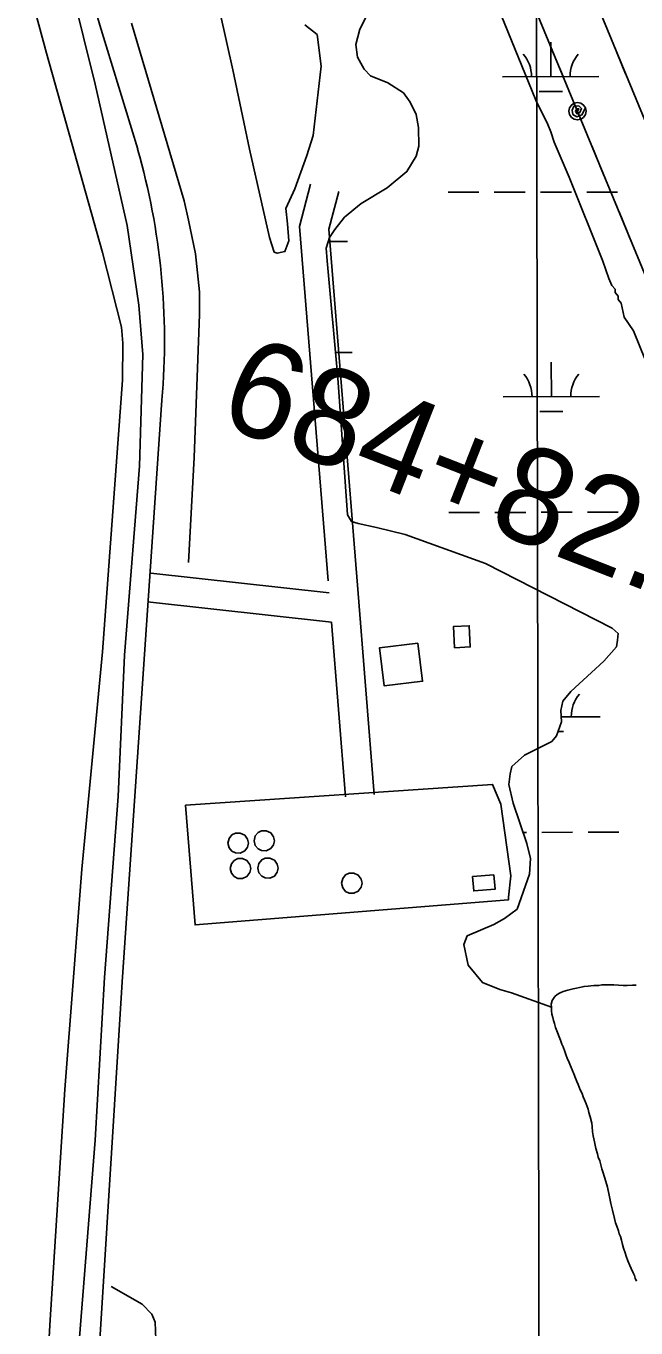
# Model space of a CAD drawing. Extents: x 3329297 to 3367176, y 649250 to 674653.
# Drawn here: x 3343401 to 3344034, y 663837 to 665190 of the extents above; entities that cross this region are included whole.
import ezdxf

# ---------------------------------------------------------------- set-up
doc = ezdxf.new("R2010")
doc.units = 0
for name, color, linetype in [('V-BLDG-OTLN', 7, 'Continuous'), ('V-DOMW-TANK', 7, 'Continuous'), ('V-DTCH-CNTR', 7, 'Continuous'), ('V-GRID-MAJR', 7, 'Continuous'), ('V-LEVE-TOET', 7, 'Continuous'), ('V-RAIL-TRAK', 7, 'Continuous'), ('V-ROAD-CNTR', 7, 'Continuous'), ('V-SITE-OTLN', 7, 'Continuous'), ('V-SITE-VEGE', 7, 'Continuous'), ('V-SURV-IDEN', 7, 'Continuous'), ('V-TOPO-SHOR', 7, 'Continuous'), ('V-UTIL-LINE', 7, 'Continuous'), ('V-WETL-SWMP', 7, 'Continuous')]:
    doc.layers.add(name, color=color, linetype=linetype)

msp = doc.modelspace()

# ---------------------------------------------------------------- linework, layer by layer
at = {"layer": 'V-BLDG-OTLN'}
for points in [[(3343846.2, 664544.3), (3343845.2, 664566.4), (3343861.4, 664567.2), (3343862.5, 664545.1)], [(3343808, 664549.2), (3343768.3, 664544.3), (3343773.2, 664504.6), (3343812.9, 664509.5)], [(3343864.9, 664306.4), (3343886.9, 664308.2), (3343888.2, 664293.3), (3343866.1, 664291.5)]]:
    msp.add_lwpolyline(points, close=True, dxfattribs=at)
at = {"layer": 'V-DOMW-TANK'}
for points in [[(3343659.2, 664343.7), (3343658.3, 664339.5), (3343655.3, 664335.5), (3343650.6, 664333.3), (3343645.8, 664333.4), (3343642.1, 664335.2), (3343639.1, 664338.7), (3343637.9, 664343.7), (3343639.1, 664348.7), (3343642.1, 664352.2), (3343645.8, 664354), (3343650.6, 664354.1), (3343655.3, 664351.9), (3343658.3, 664347.9)], [(3343632.1, 664341.3), (3343631.2, 664337), (3343628.2, 664333.1), (3343623.5, 664330.9), (3343618.7, 664331), (3343615, 664332.8), (3343612, 664336.3), (3343610.8, 664341.3), (3343612, 664346.2), (3343615, 664349.7), (3343618.7, 664351.6), (3343623.5, 664351.7), (3343628.2, 664349.5), (3343631.2, 664345.5)], [(3343634.5, 664314.9), (3343633.6, 664310.7), (3343630.6, 664306.7), (3343625.9, 664304.5), (3343621.1, 664304.6), (3343617.4, 664306.4), (3343614.4, 664309.9), (3343613.2, 664314.9), (3343614.4, 664319.8), (3343617.4, 664323.3), (3343621.1, 664325.2), (3343625.9, 664325.3), (3343630.6, 664323.1), (3343633.6, 664319.1)], [(3343663, 664315.2), (3343662.1, 664311), (3343659.1, 664307), (3343654.4, 664304.8), (3343649.6, 664305), (3343645.9, 664306.8), (3343643, 664310.3), (3343641.7, 664315.2), (3343643, 664320.2), (3343645.9, 664323.7), (3343649.6, 664325.5), (3343654.4, 664325.7), (3343659.1, 664323.5), (3343662.1, 664319.5)], [(3343750.1, 664299.6), (3343749.2, 664295.4), (3343746.2, 664291.4), (3343741.6, 664289.2), (3343736.8, 664289.3), (3343733, 664291.1), (3343730.1, 664294.6), (3343728.8, 664299.6), (3343730.1, 664304.6), (3343733, 664308.1), (3343736.8, 664309.9), (3343741.6, 664310), (3343746.2, 664307.8), (3343749.2, 664303.8)]]:
    msp.add_lwpolyline(points, close=True, dxfattribs=at)
at = {"layer": 'V-DTCH-CNTR'}
msp.add_lwpolyline([(3343489.7, 663880.5), (3343521.9, 663862.1), (3343531.8, 663851.8), (3343535.3, 663843.5), (3343537.4, 663789.2)], dxfattribs=at)
at = {"layer": 'V-GRID-MAJR'}
msp.add_spline([(3343949.3, 654651.9), (3343938.7, 660710.3), (3343928.1, 666771.7), (3343917.5, 672833.1), (3343917.5, 672836.2)], degree=3, dxfattribs=at)
at = {"layer": 'V-LEVE-TOET'}
msp.add_lwpolyline([(3343370.7, 665352.2), (3343422.3, 665162.3), (3343480.5, 664955.1), (3343500.2, 664877.4), (3343501.8, 664860.7), (3343501.5, 664822.5), (3343480.6, 664539.9), (3343459, 664314.3), (3343441.6, 664085.3), (3343425.8, 663840.4), (3343416.1, 663664.3)], dxfattribs=at)
at = {"layer": 'V-RAIL-TRAK'}
msp.add_arc((6548955.2, 1986802.1), 3466661.3, 202.398581, 202.4578394, dxfattribs=at)
at = {"layer": 'V-ROAD-CNTR'}
for points in [[(3343517.1, 665062.6), (3343477.9, 665191.4), (3343226.6, 666055.4)], [(3343714.8, 664613.7), (3343685.3, 664982.1), (3343696.7, 665025.9)], [(3343745.3, 664609.4), (3343715.6, 664979.4), (3343725.8, 665018.3)], [(3342686.8, 661326.8), (3342880.4, 661699.3), (3342918.9, 661772.4), (3342948.3, 661828.8), (3342977.9, 661900.1), (3343023.9, 662012.4), (3343199.1, 662449.7), (3343275.6, 662640.2), (3343326.1, 662763), (3343367, 662863.5), (3343386, 662912), (3343401.5, 662954.3), (3343413.8, 662991.9), (3343422.4, 663033.5), (3343430.6, 663084.8), (3343436.9, 663168.9), (3343501.1, 664197), (3343542.3, 664801.7)], [(3343530.7, 664621.7), (3343715.8, 664601.3)], [(3343762.7, 664391.7), (3343745.3, 664609.4)], [(3343527.4, 664591.9), (3343718.3, 664570.8)], [(3343732.8, 664389.3), (3343718.3, 664570.8)]]:
    msp.add_lwpolyline(points, dxfattribs=at)
msp.add_arc((3342816.2, 664863.1), 728.7, 355.1633, 15.8856, dxfattribs=at)
at = {"layer": 'V-SITE-OTLN'}
msp.add_lwpolyline([(3343566.9, 664380.5), (3343885.6, 664402.3), (3343894.1, 664381.7), (3343904.7, 664307.2), (3343902.2, 664285.1), (3343902.2, 664282.4), (3343576.7, 664256.3)], close=True, dxfattribs=at)
at = {"layer": 'V-SITE-VEGE'}
msp.add_lwpolyline([(3343690.7, 665191.6), (3343703.4, 665181.5), (3343707.7, 665148.8), (3343699.2, 665076.6), (3343692.8, 665055.7), (3343680.2, 665021.2), (3343671, 665000.6), (3343672.7, 664984.8), (3343674.1, 664967.1), (3343669.9, 664956), (3343662.1, 664954.3), (3343658.9, 664955.5), (3343654, 664970.8), (3343633.2, 665062.4), (3343616, 665145), (3343589.7, 665263)], dxfattribs=at)
at = {"layer": 'V-TOPO-SHOR'}
for points in [[(3343454.9, 663805.6), (3343472.9, 664032.6), (3343482.6, 664201.5), (3343496.9, 664389.7), (3343503.4, 664536.4), (3343519, 664733), (3343522.5, 664849.2), (3343518.4, 664900.3), (3343506.3, 664983.2), (3343472.8, 665130), (3343437.1, 665275.5), (3343388.8, 665436.1)], [(3343570, 664632.7), (3343575.6, 664742), (3343581.4, 664890.7), (3343581.2, 664914.2), (3343577.2, 664953.6), (3343569.9, 664988.8), (3343565.5, 665008.8), (3343510.7, 665193.4)], [(3343970, 664101.5), (3343968.3, 664105.6), (3343966.4, 664109.6), (3343965, 664113.3), (3343963.1, 664117.9), (3343961.9, 664120.6), (3343960.7, 664124.6), (3343958.8, 664129.4), (3343957.6, 664132.4), (3343956.1, 664136.6), (3343954.7, 664139.8), (3343953, 664144.4), (3343951.1, 664149.7), (3343949.9, 664153.9), (3343948.9, 664156.9), (3343948, 664159.9), (3343947.2, 664163.6), (3343946.7, 664166.8), (3343946.7, 664170.8), (3343946.6, 664174), (3343947.5, 664177.7), (3343950.3, 664181.9), (3343952.8, 664183.8), (3343955.8, 664185.7), (3343959, 664187.1), (3343963.6, 664188.3), (3343969.2, 664189.8), (3343972.6, 664190.5), (3343975.9, 664191.3), (3343980.7, 664192.3), (3343984.7, 664192.5), (3343987.7, 664193), (3343990.7, 664193.3), (3343995.8, 664193.4), (3343999.2, 664193.9), (3344002.3, 664193.9), (3344006.2, 664194), (3344011.5, 664193.8), (3344016.2, 664193.6), (3344021.3, 664193.4), (3344025.5, 664193.3), (3344030.8, 664193.6), (3344034.7, 664193.6)], [(3344035, 663886), (3344033.8, 663889), (3344032.8, 663892), (3344031.6, 663894.8), (3344029.5, 663899.2), (3344028, 663902.2), (3344026.1, 663907.2), (3344024.2, 663912.1), (3344023.2, 663915.3), (3344021.6, 663920.2), (3344020.6, 663924.1), (3344019.4, 663928.5), (3344018.4, 663932.4), (3344017.2, 663935.2), (3344016.2, 663938.2), (3344014.6, 663943), (3344013.4, 663946.7), (3344012.1, 663951.1), (3344010, 663959.7), (3344008.5, 663966.6), (3344007, 663973.5), (3344004.8, 663983.7), (3344003.3, 663989.5), (3344001.9, 663994.1), (3344000.2, 663999.6), (3343999.2, 664002.6), (3343998.3, 664005.6), (3343996.8, 664011), (3343995.4, 664014.9), (3343994.4, 664018.3), (3343992.7, 664023.7), (3343992, 664027.4), (3343991.5, 664030.8), (3343990.2, 664037.1), (3343989.3, 664041), (3343989, 664046.8), (3343988.5, 664050.3), (3343987, 664056.7), (3343985.6, 664061.4), (3343984.8, 664064.8), (3343982.7, 664070.4), (3343981.2, 664074.3), (3343979.8, 664077.5), (3343978.6, 664081), (3343976.7, 664084.9), (3343974.5, 664090.2), (3343973.1, 664093.4), (3343971.7, 664097.1), (3343970, 664101.5)]]:
    msp.add_lwpolyline(points, dxfattribs=at)
at = {"layer": 'V-UTIL-LINE'}
for points in [[(3345932.1, 660508.5), (3345266.9, 662132.1), (3344424.6, 664170), (3343419, 666605.5), (3342586.6, 668628.9), (3341907.6, 670274.6), (3341535.6, 671146.2)], [(3341480.8, 671097), (3341874.4, 670184.1), (3342489.4, 668700.6), (3343600.8, 666004.9), (3344292.6, 664330.1), (3345012, 662588.2), (3345711.5, 660882.6)], [(3344092, 664724.5), (3344031.8, 664873.5), (3344022.3, 664888), (3344019.1, 664902.5), (3344015.9, 664906.2), (3344015.9, 664909.8), (3344012.8, 664913.4), (3344012.8, 664917.1), (3344009.6, 664920.7), (3344006.4, 664928), (3344000.1, 664946.2), (3343965.2, 665033.4), (3343958.9, 665047.9), (3343952.6, 665062.5), (3343949.4, 665069.7), (3343946.2, 665080.6), (3343943.1, 665087.9), (3343930.4, 665113.3), (3343800.5, 665433.1)], [(3343945.9, 665169.3), (3343958.9, 665137.9)], [(3344023.7, 665140.9), (3344010.8, 665172.3)], [(3343973.8, 665101.8), (3343975.3, 665104.3), (3343973, 665104.2), (3343971.6, 665101.8), (3343973, 665099.3), (3343976.2, 665100.4), (3343978.1, 665104.7), (3343975, 665107.6), (3343970.1, 665107), (3343968.2, 665102.9), (3343968.9, 665098.5), (3343973.2, 665096.2), (3343978.4, 665098), (3343982.1, 665105.3), (3343980.1, 665108.2), (3343977.2, 665110.2), (3343973.8, 665110.8), (3343970.3, 665110.2), (3343967.4, 665108.2), (3343965.5, 665105.3), (3343964.8, 665101.9), (3343965.4, 665098.4), (3343967.4, 665095.5), (3343970.3, 665093.5), (3343973.8, 665092.8), (3343977.2, 665093.5), (3343980.1, 665095.5), (3343982.1, 665098.4), (3343982.8, 665101.8), (3343982.1, 665105.3)], [(3343988.7, 665065.8), (3344001.6, 665034.3)], [(3344016.9, 664997.4), (3344029.9, 664965.9)]]:
    msp.add_lwpolyline(points, dxfattribs=at)
at = {"layer": 'V-WETL-SWMP'}
for p, q in [((3343946, 665137.8), (3343946, 665173.8)), ((3343896, 665137.7), (3343996, 665137.9)), ((3343934.1, 665122.4), (3343958.1, 665122.4)), ((3343839.4, 665017.6), (3343871.4, 665017.6)), ((3343887.4, 665017.7), (3343919.4, 665017.7)), ((3343935.4, 665017.7), (3343967.4, 665017.8)), ((3343983.4, 665017.8), (3344015.4, 665017.9)), ((3343715, 664966.6), (3343734.9, 664966.6)), ((3343722.5, 664851.2), (3343739.7, 664851.2)), ((3343946.7, 664805.2), (3343946.6, 664841.2)), ((3343896.7, 664805.1), (3343996.7, 664805.3)), ((3343934.7, 664789.7), (3343958.7, 664789.8)), ((3343840.1, 664684.9), (3343872.1, 664685)), ((3343888.1, 664685), (3343920.1, 664685)), ((3343936.1, 664685.1), (3343968.1, 664685.1)), ((3343984.1, 664685.2), (3344016.1, 664685.2)), ((3343957, 664472.5), (3343997.3, 664472.6)), ((3343953.6, 664457.1), (3343959.3, 664457.1)), ((3343917.4, 664352.4), (3343920.7, 664352.4)), ((3343936.7, 664352.4), (3343968.7, 664352.5)), ((3343984.7, 664352.5), (3344016.7, 664352.6))]:
    msp.add_line(p, q, dxfattribs=at)
for points in [[(3343947.1, 664447), (3343951.9, 664452.6), (3343957.3, 664467.3), (3343956.5, 664479.1), (3343958.5, 664488.9), (3343966.7, 664498.7), (3344001.1, 664530.4), (3344014.1, 664545.2), (3344015.4, 664552.2), (3344016, 664559.1), (3344009.7, 664564.6), (3343878.1, 664631.9), (3343795, 664662.1), (3343765, 664669.4), (3343746.2, 664673.4), (3343739.2, 664675.4), (3343735, 664682.3), (3343724.9, 664824.7), (3343713.7, 664946.3), (3343712.9, 664959.5), (3343716.2, 664970.6), (3343721.7, 664979.1), (3343731.9, 664991.7), (3343749.1, 665005.8), (3343776.1, 665022.1), (3343796.7, 665039.1), (3343806.3, 665055.2), (3343808.9, 665065.6), (3343808.7, 665085.1), (3343806.4, 665098.3), (3343800, 665111.4), (3343793, 665121.1), (3343776.8, 665131.3), (3343758.7, 665138.7), (3343752.3, 665145.6), (3343745.2, 665158.1), (3343743.7, 665171.2), (3343747.6, 665187.3), (3343755.1, 665201.3)], [(3344034.7, 664193.6), (3344030.8, 664193.6), (3344025.4, 664193.3), (3344021.3, 664193.4), (3344016.2, 664193.6), (3344011.5, 664193.8), (3344006.2, 664194), (3344002.3, 664193.9), (3343999.2, 664193.9), (3343995.8, 664193.4), (3343990.7, 664193.3), (3343987.7, 664193), (3343984.7, 664192.5), (3343980.7, 664192.3), (3343975.9, 664191.3), (3343972.6, 664190.5), (3343969.2, 664189.8), (3343963.6, 664188.3), (3343959, 664187.1), (3343955.8, 664185.7), (3343952.8, 664183.8), (3343950.3, 664181.9), (3343947.5, 664177.7), (3343946.6, 664174), (3343946.7, 664170.8), (3343905.1, 664185.7), (3343893.2, 664189.1), (3343875.1, 664196.5), (3343860.2, 664214.4), (3343855.8, 664235.9), (3343859.2, 664245), (3343886.9, 664256.5), (3343897.9, 664262.8), (3343911, 664272.7), (3343923.8, 664309.1), (3343925, 664325.1), (3343921.3, 664341), (3343906.9, 664382.6), (3343902.5, 664402), (3343903.7, 664413.1), (3343905.7, 664420.8), (3343918.8, 664432.8), (3343947.1, 664447)]]:
    msp.add_lwpolyline(points, dxfattribs=at)
for centre, start, end in [((3343890.8, 665138.2), 359.3365, 40.8801), ((3344001.3, 665138.4), 139.3365, 180.8801), ((3343891.4, 664805.5), 359.3365, 40.8801), ((3344001.9, 664805.7), 139.3365, 180.8801), ((3344002.5, 664473.1), 139.3365, 180.8801)]:
    msp.add_arc(centre, 35.2, start, end, dxfattribs=at)

# ---------------------------------------------------------------- texts
at = {"layer": 'V-SURV-IDEN'}
msp.add_text('684+82.1', height=100, rotation=338.5856, dxfattribs=at).set_placement((3343597.3, 664778.6))

doc.saveas('drawing.dxf')
